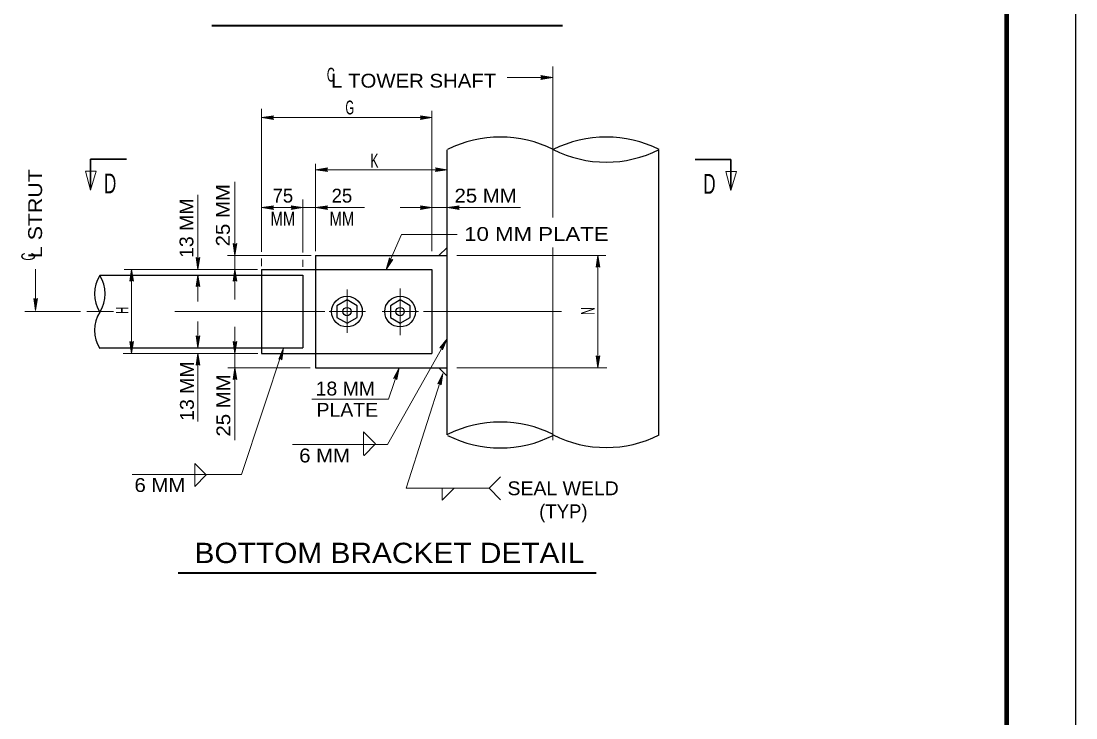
# Model space of a CAD drawing. Extents: x 312601.858 to 312602.699, y 144420.109 to 144420.704.
# Drawn here: x 312602.4702 to 312602.6988, y 144420.3942 to 144420.5451 of the extents above; entities that cross this region are included whole.
import ezdxf
from ezdxf.enums import TextEntityAlignment as Align

# ---------------------------------------------------------------- set-up
doc = ezdxf.new("R2010")
doc.units = 0
doc.header["$LTSCALE"] = 0.0012
doc.linetypes.add('DOT_DASHED', pattern=[7.7, 5, -1.2, 0.3, -1.2])
doc.linetypes.add('MEDIUM_DASHED', pattern=[4.5, 3, -1.5])
for name, color, linetype, lineweight in [('1', 7, 'Continuous', 25), ('2', 7, 'Continuous', 13), ('39', 7, 'Continuous', 13), ('9', 7, 'Continuous', 13)]:
    doc.layers.add(name, color=color, linetype=linetype, lineweight=lineweight)

msp = doc.modelspace()

# ---------------------------------------------------------------- hatches: boundary and pattern name
at = {"layer": '39'}
for points in [[(312602.5831, 144420.5329), (312602.5828, 144420.5333), (312602.5854, 144420.5329), (312602.5828, 144420.5325)], [(312602.5246, 144420.5242), (312602.5249, 144420.5238), (312602.5223, 144420.5242), (312602.5249, 144420.5246)], [(312602.5569, 144420.5242), (312602.5567, 144420.5246), (312602.5592, 144420.5242), (312602.5567, 144420.5238)], [(312602.5363, 144420.5129), (312602.5366, 144420.5125), (312602.534, 144420.5129), (312602.5366, 144420.5133)], [(312602.5363, 144420.5129), (312602.5366, 144420.5125), (312602.534, 144420.5129), (312602.5366, 144420.5133)], [(312602.5602, 144420.5129), (312602.56, 144420.5133), (312602.5625, 144420.5129), (312602.56, 144420.5125)], [(312602.5246, 144420.5047), (312602.5249, 144420.5043), (312602.5223, 144420.5047), (312602.5249, 144420.5051)], [(312602.5246, 144420.5047), (312602.5249, 144420.5043), (312602.5223, 144420.5047), (312602.5249, 144420.5051)], [(312602.5289, 144420.5047), (312602.5287, 144420.5051), (312602.5312, 144420.5047), (312602.5287, 144420.5043)], [(312602.5289, 144420.5047), (312602.5287, 144420.5051), (312602.5312, 144420.5047), (312602.5287, 144420.5043)], [(312602.5363, 144420.5047), (312602.5366, 144420.5043), (312602.534, 144420.5047), (312602.5366, 144420.5051)], [(312602.5569, 144420.5047), (312602.5567, 144420.5051), (312602.5592, 144420.5047), (312602.5567, 144420.5043)], [(312602.5569, 144420.5047), (312602.5567, 144420.5051), (312602.5592, 144420.5047), (312602.5567, 144420.5043)], [(312602.5648, 144420.5047), (312602.5651, 144420.5043), (312602.5625, 144420.5047), (312602.5651, 144420.5051)], [(312602.5648, 144420.5047), (312602.5651, 144420.5043), (312602.5625, 144420.5047), (312602.5651, 144420.5051)], [(312602.5165, 144420.4966), (312602.5169, 144420.4969), (312602.5165, 144420.4943), (312602.5161, 144420.4969)], [(312602.5085, 144420.4936), (312602.5089, 144420.4939), (312602.5085, 144420.4913), (312602.5081, 144420.4939)], [(312602.5502, 144420.4934), (312602.5507, 144420.4935), (312602.5493, 144420.4913), (312602.55, 144420.4938)], [(312602.5952, 144420.492), (312602.5948, 144420.4918), (312602.5952, 144420.4943), (312602.5956, 144420.4918)], [(312602.4941, 144420.489), (312602.4937, 144420.4888), (312602.4941, 144420.4913), (312602.4945, 144420.4888)], [(312602.5085, 144420.4878), (312602.5081, 144420.4876), (312602.5085, 144420.4901), (312602.5089, 144420.4876)], [(312602.5165, 144420.489), (312602.5161, 144420.4888), (312602.5165, 144420.4913), (312602.5169, 144420.4888)], [(312602.4733, 144420.4847), (312602.4737, 144420.485), (312602.4733, 144420.4824), (312602.4729, 144420.485)], [(312602.4733, 144420.4847), (312602.4737, 144420.485), (312602.4733, 144420.4824), (312602.4729, 144420.485)], [(312602.5085, 144420.4766), (312602.5089, 144420.4769), (312602.5085, 144420.4743), (312602.5081, 144420.4769)], [(312602.4941, 144420.4754), (312602.4945, 144420.4757), (312602.4941, 144420.4731), (312602.4937, 144420.4757)], [(312602.5165, 144420.4754), (312602.5169, 144420.4757), (312602.5165, 144420.4731), (312602.5161, 144420.4757)], [(312602.5264, 144420.4721), (312602.526, 144420.4719), (312602.527, 144420.4743), (312602.5267, 144420.4717)], [(312602.5613, 144420.4743), (312602.5609, 144420.4743), (312602.5625, 144420.4763), (312602.5615, 144420.4739)], [(312602.5085, 144420.4708), (312602.5081, 144420.4706), (312602.5085, 144420.4731), (312602.5089, 144420.4706)], [(312602.5952, 144420.4723), (312602.5956, 144420.4726), (312602.5952, 144420.47), (312602.5948, 144420.4726)], [(312602.5165, 144420.4677), (312602.5161, 144420.4675), (312602.5165, 144420.47), (312602.5169, 144420.4675)], [(312602.5514, 144420.4678), (312602.5509, 144420.4677), (312602.5521, 144420.47), (312602.5516, 144420.4675)], [(312602.5609, 144420.4666), (312602.5605, 144420.4665), (312602.5616, 144420.4688), (312602.5612, 144420.4663)], [(312602.5609, 144420.4666), (312602.5605, 144420.4665), (312602.5616, 144420.4688), (312602.5612, 144420.4663)]]:
    msp.add_hatch(color=256, dxfattribs=at).paths.add_polyline_path(points)

# ---------------------------------------------------------------- linework, layer by layer
at = {"layer": '1', "lineweight": 13}
for p, q in [((312602.5854, 144420.5353), (312602.5854, 144420.5215)), ((312602.5854, 144420.5329), (312602.5755, 144420.5329)), ((312602.5223, 144420.5261), (312602.5223, 144420.4951)), ((312602.5592, 144420.5257), (312602.5592, 144420.4953)), ((312602.5592, 144420.5242), (312602.5223, 144420.5242)), ((312602.534, 144420.5142), (312602.534, 144420.4953)), ((312602.5625, 144420.5129), (312602.534, 144420.5129)), ((312602.5085, 144420.5075), (312602.5085, 144420.4913)), ((312602.5312, 144420.5065), (312602.5312, 144420.495)), ((312602.5625, 144420.5047), (312602.5784, 144420.5047)), ((312602.5149, 144420.4943), (312602.533, 144420.4943)), ((312602.5223, 144420.4937), (312602.5223, 144420.492)), ((312602.5312, 144420.4934), (312602.5312, 144420.4919)), ((312602.5646, 144420.4943), (312602.5969, 144420.4943)), ((312602.4733, 144420.4914), (312602.4733, 144420.4824)), ((312602.4925, 144420.4913), (312602.5214, 144420.4913)), ((312602.4941, 144420.4913), (312602.4941, 144420.4731)), ((312602.5085, 144420.4901), (312602.5085, 144420.4844)), ((312602.5165, 144420.4913), (312602.5165, 144420.4848)), ((312602.471, 144420.4822), (312602.483, 144420.4822)), ((312602.5085, 144420.48), (312602.5085, 144420.4743)), ((312602.5165, 144420.4789), (312602.5165, 144420.4731)), ((312602.527, 144420.4743), (312602.5179, 144420.4469)), ((312602.5625, 144420.4763), (312602.5496, 144420.4534)), ((312602.4923, 144420.4731), (312602.5215, 144420.4731)), ((312602.5085, 144420.4731), (312602.5085, 144420.4584)), ((312602.5165, 144420.4731), (312602.5165, 144420.47)), ((312602.515, 144420.47), (312602.5328, 144420.47)), ((312602.5165, 144420.47), (312602.5165, 144420.4543)), ((312602.5646, 144420.47), (312602.5971, 144420.47)), ((312602.529, 144420.4534), (312602.5496, 144420.4534)), ((312602.4942, 144420.4469), (312602.5179, 144420.4469)), ((312602.5614, 144420.4439), (312602.5614, 144420.4413)), ((312602.5614, 144420.4413), (312602.564, 144420.4439))]:
    msp.add_line(p, q, dxfattribs=at)
at = {"layer": '1', "linetype": 'DOT_DASHED', "lineweight": 13}
for p, q in [((312602.5854, 144420.5218), (312602.5854, 144420.5026)), ((312602.5854, 144420.4961), (312602.5854, 144420.4543)), ((312602.5408, 144420.487), (312602.5408, 144420.4776)), ((312602.5523, 144420.4872), (312602.5523, 144420.4773)), ((312602.5523, 144420.487), (312602.5523, 144420.4771)), ((312602.4844, 144420.4822), (312602.4902, 144420.4822)), ((312602.5035, 144420.4822), (312602.536, 144420.4822)), ((312602.5369, 144420.4822), (312602.5448, 144420.4822)), ((312602.5484, 144420.4822), (312602.5563, 144420.4822)), ((312602.5574, 144420.4822), (312602.5873, 144420.4822))]:
    msp.add_line(p, q, dxfattribs=at)
at = {"layer": '1'}
for p, q in [((312602.5625, 144420.4555), (312602.5625, 144420.5172)), ((312602.6084, 144420.4554), (312602.6084, 144420.5172)), ((312602.534, 144420.4943), (312602.534, 144420.4913)), ((312602.534, 144420.4943), (312602.5625, 144420.4943)), ((312602.4872, 144420.4901), (312602.5312, 144420.4901)), ((312602.5223, 144420.4913), (312602.5592, 144420.4913)), ((312602.5223, 144420.4913), (312602.5223, 144420.4901)), ((312602.5312, 144420.4901), (312602.5312, 144420.4743)), ((312602.5592, 144420.4913), (312602.5592, 144420.4731)), ((312602.4872, 144420.4743), (312602.5312, 144420.4743)), ((312602.5223, 144420.4743), (312602.5223, 144420.4731)), ((312602.5223, 144420.4731), (312602.5592, 144420.4731)), ((312602.534, 144420.4731), (312602.534, 144420.47)), ((312602.534, 144420.47), (312602.5625, 144420.47))]:
    msp.add_line(p, q, dxfattribs=at)
at = {"layer": '1', "linetype": 'MEDIUM_DASHED'}
for p, q in [((312602.5223, 144420.4901), (312602.5223, 144420.4743)), ((312602.534, 144420.4913), (312602.534, 144420.4731))]:
    msp.add_line(p, q, dxfattribs=at)
at = {"layer": '1', "lineweight": 35}
for points in [[(312602.4852, 144420.5089), (312602.4852, 144420.5152), (312602.493, 144420.5152)], [(312602.624, 144420.5088), (312602.624, 144420.5151), (312602.6163, 144420.5151)]]:
    msp.add_lwpolyline(points, dxfattribs=at)
at = {"layer": '1', "lineweight": 13}
for points in [[(312602.5165, 144420.5103), (312602.5165, 144420.4943), (312602.5165, 144420.4913)], [(312602.5223, 144420.5047), (312602.5312, 144420.5047), (312602.534, 144420.5047), (312602.5446, 144420.5047)], [(312602.5523, 144420.5047), (312602.5592, 144420.5047), (312602.5625, 144420.5047)], [(312602.5493, 144420.4913), (312602.5526, 144420.4989), (312602.5647, 144420.4989)], [(312602.5521, 144420.47), (312602.5498, 144420.4632), (312602.5332, 144420.4632)]]:
    msp.add_lwpolyline(points, dxfattribs=at)
at = {"layer": '1'}
for points in [[(312602.5408, 144420.4797), (312602.543, 144420.4809), (312602.543, 144420.4834), (312602.5408, 144420.4847), (312602.5386, 144420.4834), (312602.5386, 144420.4809)], [(312602.5523, 144420.4797), (312602.5545, 144420.4809), (312602.5545, 144420.4834), (312602.5523, 144420.4847), (312602.5502, 144420.4834), (312602.5502, 144420.4809)]]:
    msp.add_lwpolyline(points, close=True, dxfattribs=at)
at = {"layer": '1', "lineweight": 13}
msp.add_lwpolyline([(312602.5444, 144420.4511), (312602.5444, 144420.4561), (312602.547, 144420.4535), (312602.5445, 144420.451)], close=True, dxfattribs=at)
at = {"layer": '1'}
for centre, radius in [((312602.54079, 144420.48218), 0.00333), ((312602.55231, 144420.48218), 0.00333), ((312602.54079, 144420.48218), 0.0009), ((312602.55231, 144420.48218), 0.0009)]:
    msp.add_circle(centre, radius, dxfattribs=at)
at = {"layer": '2', "lineweight": 40}
for p, q in [((312602.5115, 144420.5442), (312602.5875, 144420.5442)), ((312602.5042, 144420.4256), (312602.5948, 144420.4256))]:
    msp.add_line(p, q, dxfattribs=at)
at = {"layer": '2'}
msp.add_line((312602.5952, 144420.4943), (312602.5952, 144420.47), dxfattribs=at)
for points in [[(312602.5616, 144420.4688), (312602.5536, 144420.4439), (312602.5716, 144420.4439)], [(312602.5741, 144420.4414), (312602.5716, 144420.4439), (312602.5741, 144420.4464)]]:
    msp.add_lwpolyline(points, dxfattribs=at)
msp.add_lwpolyline([(312602.5078, 144420.4493), (312602.5078, 144420.4443), (312602.5103, 144420.4468)], close=True, dxfattribs=at)
at = {"layer": '2', "lineweight": 25}
for centre, radius, start, end in [((312602.574045, 144420.494381), 0.025613, 63.38393, 116.61607), ((312602.596995, 144420.494381), 0.025613, 63.38393, 116.61607), ((312602.596995, 144420.540179), 0.025613, 243.38393, 296.61607), ((312602.493323, 144420.48605), 0.007275, 147.02071, 212.97929), ((312602.481117, 144420.48605), 0.007275, 327.02071, 32.97929), ((312602.493323, 144420.47813), 0.007275, 147.02071, 212.97929), ((312602.574045, 144420.432641), 0.025613, 63.38393, 116.61607), ((312602.574045, 144420.478259), 0.025613, 243.38393, 296.61607), ((312602.596995, 144420.478349), 0.025613, 243.38393, 296.61607)]:
    msp.add_arc(centre, radius, start, end, dxfattribs=at)
at = {"layer": '39', "lineweight": 25}
msp.add_line((312602.6988, 144420.1095), (312602.6988, 144420.7035), dxfattribs=at)
at = {"layer": '39', "lineweight": 158}
msp.add_line((312602.6838, 144420.1247), (312602.6838, 144420.6645), dxfattribs=at)
at = {"layer": '39'}
for points in [[(312602.5831, 144420.5329), (312602.5828, 144420.5333), (312602.5854, 144420.5329), (312602.5828, 144420.5325)], [(312602.5246, 144420.5242), (312602.5249, 144420.5238), (312602.5223, 144420.5242), (312602.5249, 144420.5246)], [(312602.5569, 144420.5242), (312602.5567, 144420.5246), (312602.5592, 144420.5242), (312602.5567, 144420.5238)], [(312602.5363, 144420.5129), (312602.5366, 144420.5125), (312602.534, 144420.5129), (312602.5366, 144420.5133)], [(312602.5363, 144420.5129), (312602.5366, 144420.5125), (312602.534, 144420.5129), (312602.5366, 144420.5133)], [(312602.5602, 144420.5129), (312602.56, 144420.5133), (312602.5625, 144420.5129), (312602.56, 144420.5125)], [(312602.5246, 144420.5047), (312602.5249, 144420.5043), (312602.5223, 144420.5047), (312602.5249, 144420.5051)], [(312602.5246, 144420.5047), (312602.5249, 144420.5043), (312602.5223, 144420.5047), (312602.5249, 144420.5051)], [(312602.5289, 144420.5047), (312602.5287, 144420.5051), (312602.5312, 144420.5047), (312602.5287, 144420.5043)], [(312602.5289, 144420.5047), (312602.5287, 144420.5051), (312602.5312, 144420.5047), (312602.5287, 144420.5043)], [(312602.5363, 144420.5047), (312602.5366, 144420.5043), (312602.534, 144420.5047), (312602.5366, 144420.5051)], [(312602.5569, 144420.5047), (312602.5567, 144420.5051), (312602.5592, 144420.5047), (312602.5567, 144420.5043)], [(312602.5569, 144420.5047), (312602.5567, 144420.5051), (312602.5592, 144420.5047), (312602.5567, 144420.5043)], [(312602.5648, 144420.5047), (312602.5651, 144420.5043), (312602.5625, 144420.5047), (312602.5651, 144420.5051)], [(312602.5648, 144420.5047), (312602.5651, 144420.5043), (312602.5625, 144420.5047), (312602.5651, 144420.5051)], [(312602.5165, 144420.4966), (312602.5169, 144420.4969), (312602.5165, 144420.4943), (312602.5161, 144420.4969)], [(312602.5085, 144420.4936), (312602.5089, 144420.4939), (312602.5085, 144420.4913), (312602.5081, 144420.4939)], [(312602.5502, 144420.4934), (312602.5507, 144420.4935), (312602.5493, 144420.4913), (312602.55, 144420.4938)], [(312602.5952, 144420.492), (312602.5948, 144420.4918), (312602.5952, 144420.4943), (312602.5956, 144420.4918)], [(312602.4941, 144420.489), (312602.4937, 144420.4888), (312602.4941, 144420.4913), (312602.4945, 144420.4888)], [(312602.5085, 144420.4878), (312602.5081, 144420.4876), (312602.5085, 144420.4901), (312602.5089, 144420.4876)], [(312602.5165, 144420.489), (312602.5161, 144420.4888), (312602.5165, 144420.4913), (312602.5169, 144420.4888)], [(312602.4733, 144420.4847), (312602.4737, 144420.485), (312602.4733, 144420.4824), (312602.4729, 144420.485)], [(312602.4733, 144420.4847), (312602.4737, 144420.485), (312602.4733, 144420.4824), (312602.4729, 144420.485)], [(312602.5085, 144420.4766), (312602.5089, 144420.4769), (312602.5085, 144420.4743), (312602.5081, 144420.4769)], [(312602.4941, 144420.4754), (312602.4945, 144420.4757), (312602.4941, 144420.4731), (312602.4937, 144420.4757)], [(312602.5165, 144420.4754), (312602.5169, 144420.4757), (312602.5165, 144420.4731), (312602.5161, 144420.4757)], [(312602.5264, 144420.4721), (312602.526, 144420.4719), (312602.527, 144420.4743), (312602.5267, 144420.4717)], [(312602.5613, 144420.4743), (312602.5609, 144420.4743), (312602.5625, 144420.4763), (312602.5615, 144420.4739)], [(312602.5085, 144420.4708), (312602.5081, 144420.4706), (312602.5085, 144420.4731), (312602.5089, 144420.4706)], [(312602.5952, 144420.4723), (312602.5956, 144420.4726), (312602.5952, 144420.47), (312602.5948, 144420.4726)], [(312602.5165, 144420.4677), (312602.5161, 144420.4675), (312602.5165, 144420.47), (312602.5169, 144420.4675)], [(312602.5514, 144420.4678), (312602.5509, 144420.4677), (312602.5521, 144420.47), (312602.5516, 144420.4675)], [(312602.5609, 144420.4666), (312602.5605, 144420.4665), (312602.5616, 144420.4688), (312602.5612, 144420.4663)], [(312602.5609, 144420.4666), (312602.5605, 144420.4665), (312602.5616, 144420.4688), (312602.5612, 144420.4663)]]:
    msp.add_lwpolyline(points, close=True, dxfattribs=at)
at = {"layer": '9'}
for points in [[(312602.4841, 144420.5126), (312602.4852, 144420.5085), (312602.4864, 144420.5126)], [(312602.624, 144420.5084), (312602.6252, 144420.5125), (312602.6229, 144420.5125)], [(312602.5607, 144420.4943), (312602.5625, 144420.4943), (312602.5625, 144420.4961)], [(312602.5607, 144420.47), (312602.5625, 144420.4682), (312602.5625, 144420.47)]]:
    msp.add_lwpolyline(points, close=True, dxfattribs=at)

# ---------------------------------------------------------------- texts
at = {"layer": '1'}
for s, width, p in [('10 MM PLATE', 1.2, (312602.5662, 144420.4975)), ('18 MM', 1.05, (312602.534, 144420.464)), ('PLATE', 1.05, (312602.5342, 144420.4594))]:
    msp.add_text(s, height=0.003, dxfattribs=dict(at, width=width)).set_placement(p)
at = {"layer": '2'}
for s, height, width, p in [('C', 0.003, 0.6, (312602.5373, 144420.532)), ('L TOWER SHAFT', 0.003, 1.1, (312602.55525, 144420.5307)), ('G', 0.003, 0.6, (312602.5414, 144420.5249)), ('K', 0.003, 0.65, (312602.54675, 144420.5134)), ('D', 0.0043, 0.65, (312602.48945, 144420.5078)), ('D', 0.0043, 0.65, (312602.61935, 144420.5077)), ('25 MM', 0.003, 1.1, (312602.57085, 144420.5058)), ('MM', 0.003, 0.8, (312602.5269, 144420.5008)), ('MM', 0.003, 0.8, (312602.5397, 144420.5008)), ('6 MM', 0.003, 1.1, (312602.53595, 144420.4495)), ('6 MM', 0.003, 1.1, (312602.50025, 144420.4431)), ('SEAL WELD', 0.003, 1.05, (312602.58765, 144420.4424)), ('BOTTOM BRACKET DETAIL', 0.0044, 1.1, (312602.55, 144420.4277))]:
    msp.add_text(s, height=height, dxfattribs=dict(at, width=width)).set_placement(p, align=Align.CENTER)
for s, height, width, p in [('L STRUT', 0.003, 1.15, (312602.4747, 144420.5034)), ('25 MM', 0.003, 1.1, (312602.5154, 144420.50305)), ('13 MM', 0.003, 1.05, (312602.5075, 144420.50025)), ('C', 0.003, 0.6, (312602.4732, 144420.4941)), ('H', 0.0027, 0.55, (312602.4934, 144420.48245)), ('N', 0.003, 0.6, (312602.5945, 144420.4823)), ('13 MM', 0.003, 1.05, (312602.5076, 144420.46495)), ('25 MM', 0.003, 1.1, (312602.5155, 144420.46185))]:
    msp.add_text(s, height=height, rotation=90, dxfattribs=dict(at, width=width)).set_placement(p, align=Align.CENTER)
for s, p in [('75', (312602.5269, 144420.5058)), ('25', (312602.5397, 144420.5058)), ('(TYP)', (312602.5877, 144420.4374))]:
    msp.add_text(s, height=0.003, dxfattribs=at).set_placement(p, align=Align.CENTER)

doc.saveas('drawing.dxf')
